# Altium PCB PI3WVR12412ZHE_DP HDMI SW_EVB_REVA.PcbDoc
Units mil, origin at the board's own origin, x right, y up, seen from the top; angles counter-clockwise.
Board outline 3803 x 3400 mil, 4 copper layers (Top Layer, InternalPlane1, InternalPlane2, Bottom Layer); 70 components, 74 nets, 324 pads, 131 vias.
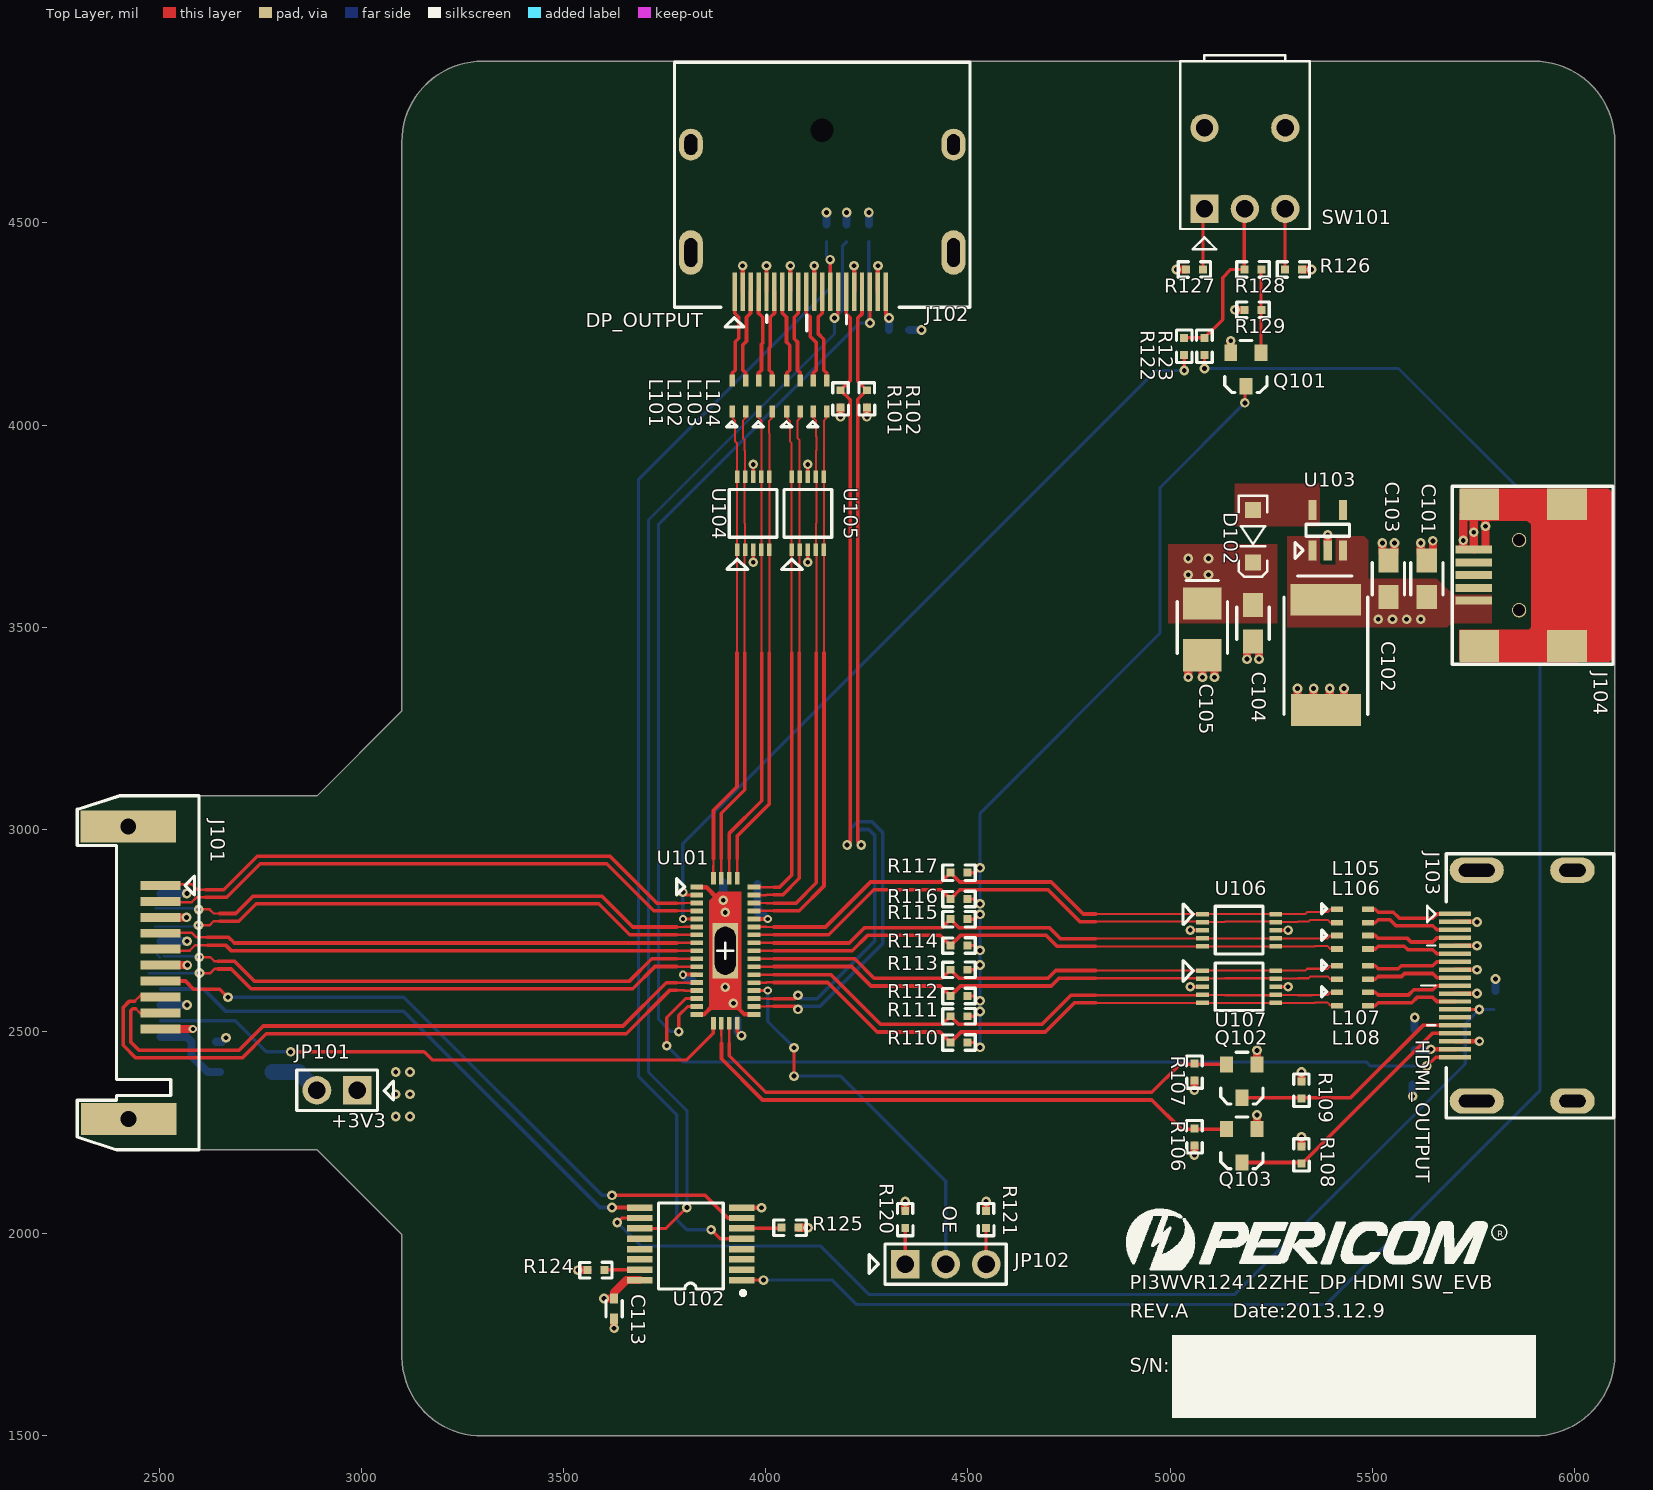
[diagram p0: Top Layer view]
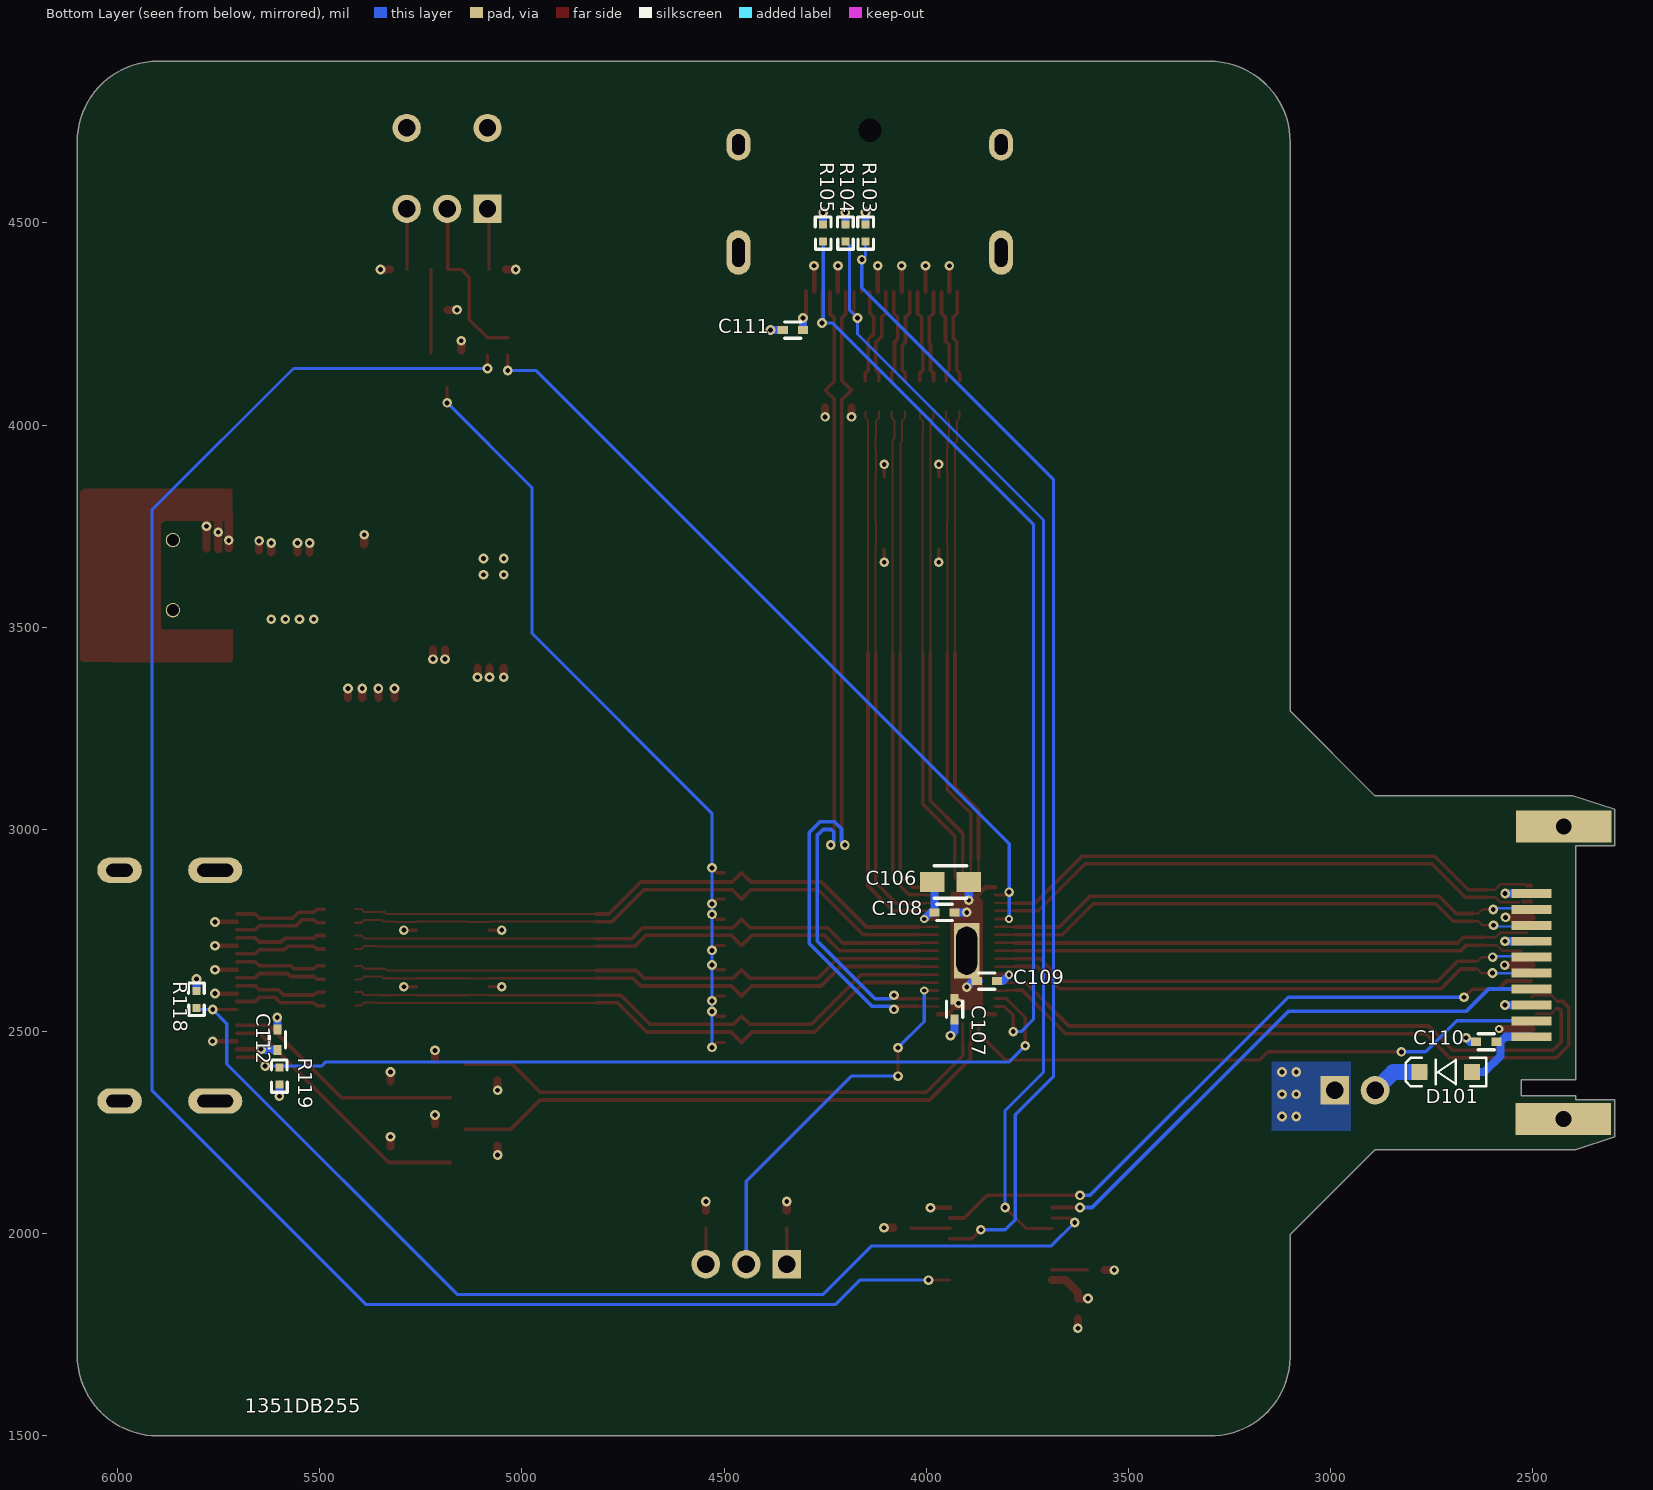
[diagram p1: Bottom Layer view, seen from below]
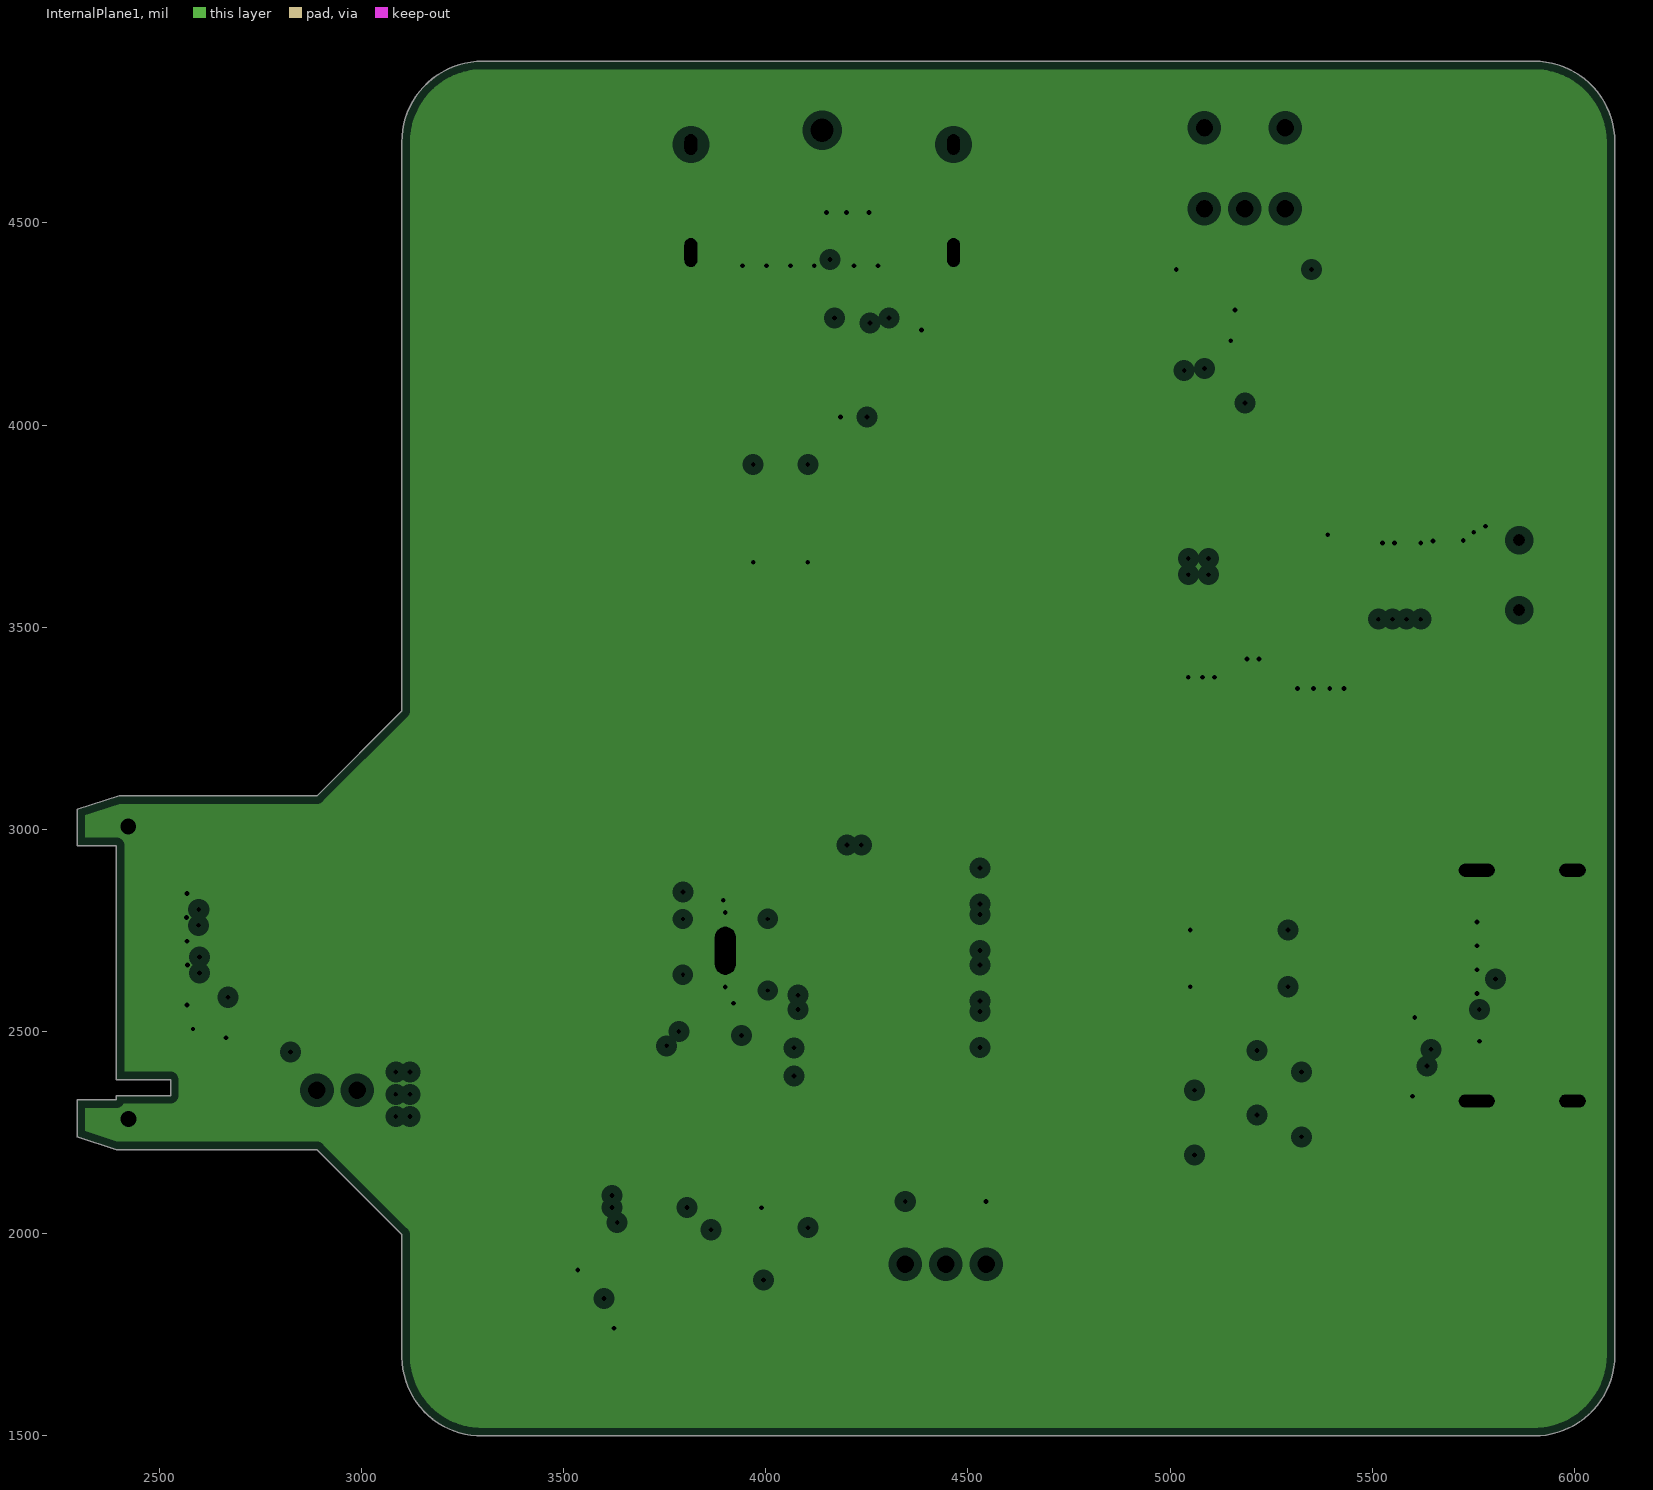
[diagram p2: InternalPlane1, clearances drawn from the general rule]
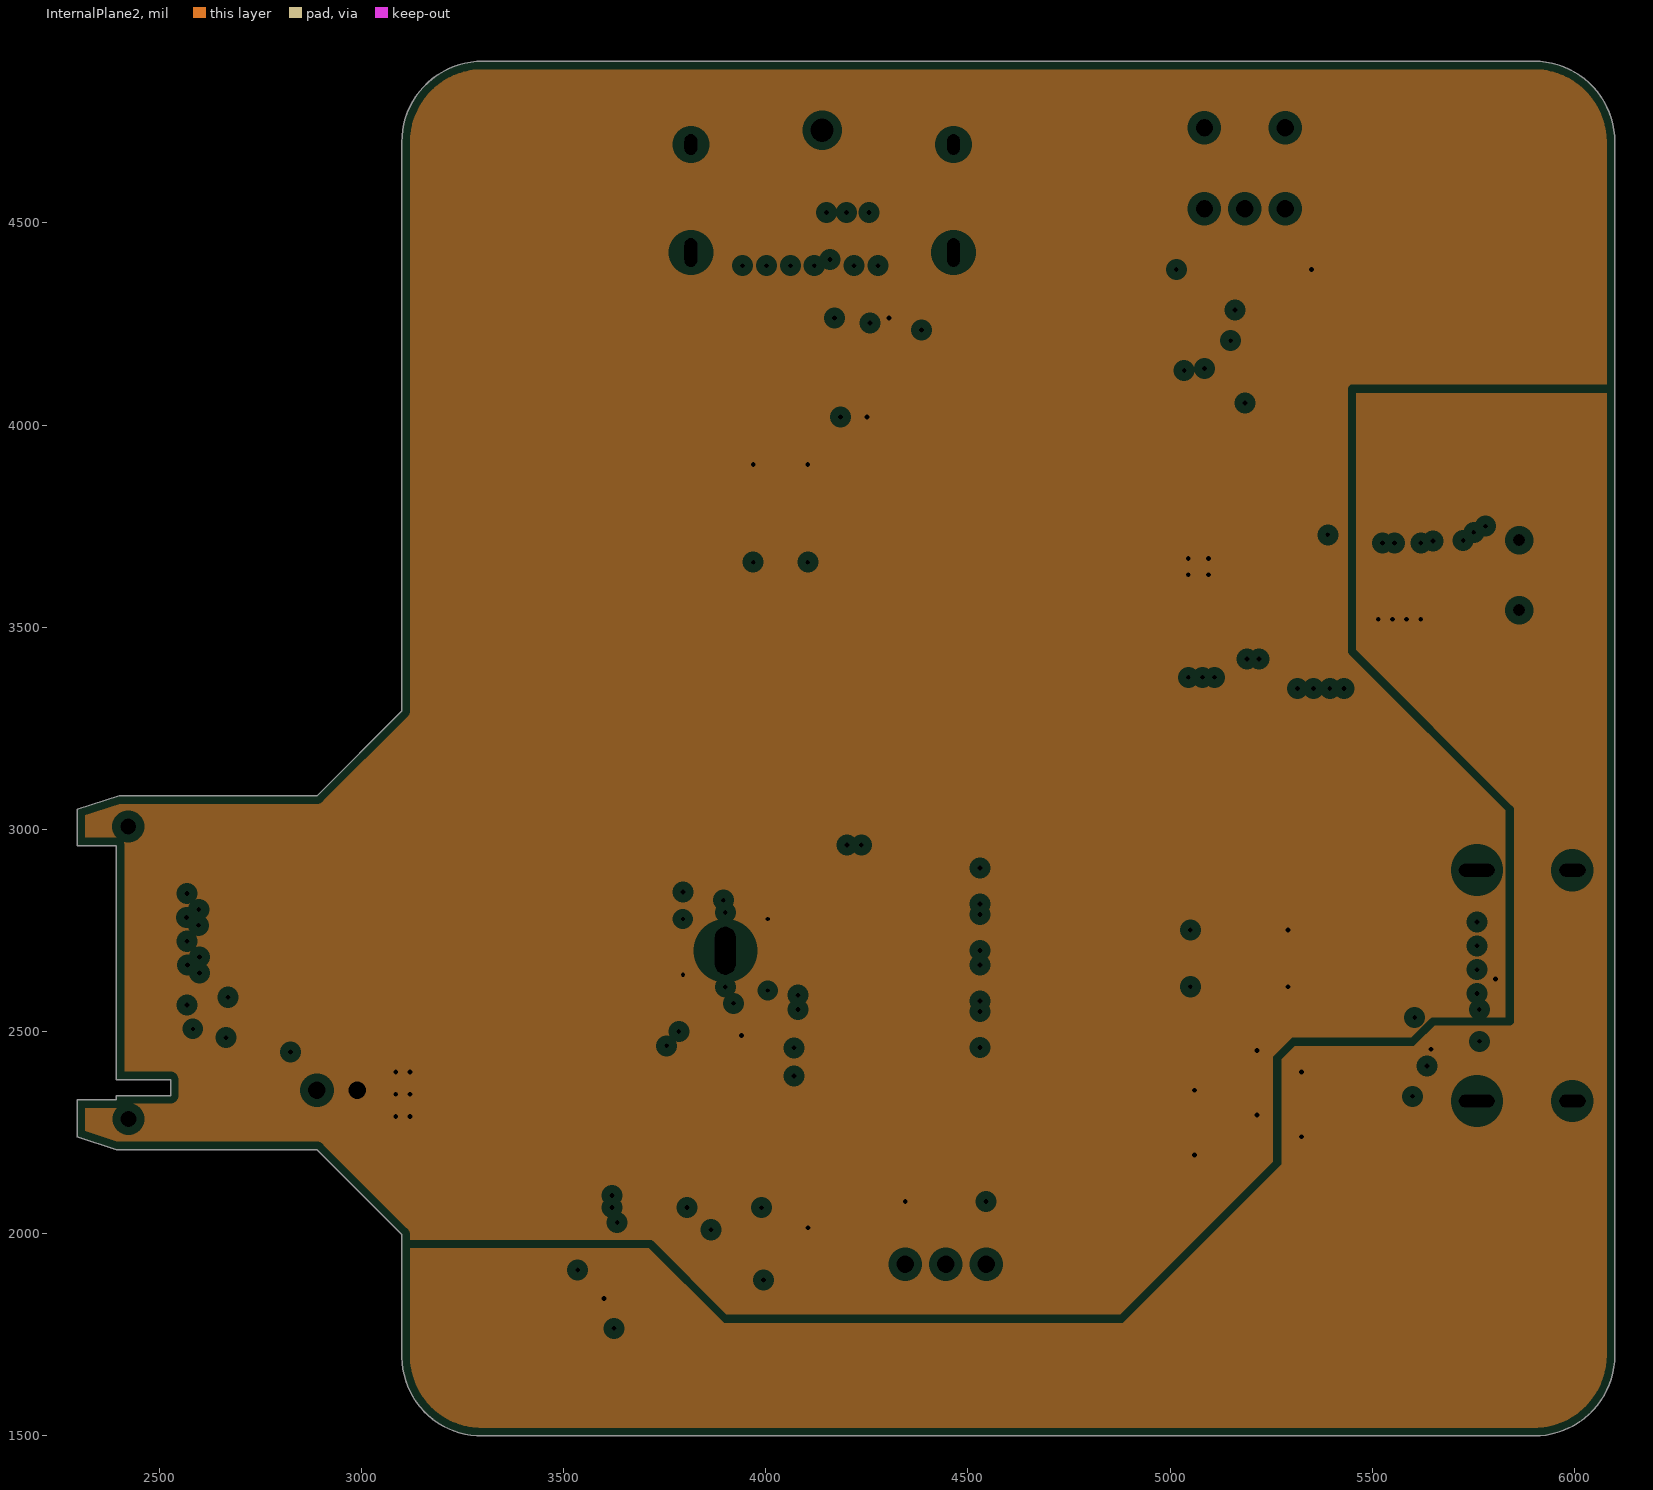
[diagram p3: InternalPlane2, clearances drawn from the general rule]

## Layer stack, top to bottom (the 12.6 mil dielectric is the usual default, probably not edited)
Top Layer: signal copper 1.4
Dielectric: core 12.6, FR-4, Dk 4.8
InternalPlane1: plane copper 1.4, net GND
Dielectric: prepreg 12.6, FR-4, Dk 4.8
InternalPlane2: plane copper 1.4, net +3V3
Dielectric: core 12.6, FR-4, Dk 4.8
Bottom Layer: signal copper 1.4

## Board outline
2297,2240 2394,2208 2890,2208 3100,1998 3100,1695 ccw(c3297.5,1697.5) 3300,1500 5900,1500 ccw(c5900,1700) 6100,1700 6100,4700 ccw(c5900,4700) 5900,4900 3300,4900 ccw(c3300,4700) 3100,4700 3100,3293 2890,3083 2401,3083 2297,3050 2297,2960 2394,2960 2394,2381 2528,2381 2528,2342 2394,2342 2394,2331 2297,2331

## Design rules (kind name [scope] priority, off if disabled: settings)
Clearance [All] p1: gap=5
ComponentClearance [All] p1: gap=0 collisioncheckmode=3 verticalgap=0
DiffPairsRouting [All] p1: maxlimit=10 minlimit=10 mostfreqgap=10 maxuncoupledlength=500
HoleSize [All] p1: absolutevalues=TRUE maxlimit=500 minlimit=1 maxpercent=80.000 minpercent=20.000
PlaneClearance [All] p1: clearance=20
PlaneConnect [All] p1: planeconnectstyle=Direct reliefexpansion=20 reliefentries=4 reliefconductorwidth=10 reliefairgap=10
PolygonConnect [All] p1: connectstyle=Direct reliefconductorwidth=10 reliefentries=4 polygonreliefangle="90 Angle"
RoomDefinition "PI3WVR12412_DP HDMI_EVB" [InComponentClass('PI3WVR12412_DP HDMI_EVB')] p1: confinementstyle=ConfineIn formatcopy=TRUE lockcomponents=FALSE outline 120,25 27240,25 27240,6930 120,6930
RoutingVias [All] p1: holewidth=28 width=50 viastyle="Through Hole" minholewidth=8 minwidth=10 maxholewidth=28 maxwidth=50
SolderMaskExpansion [All] p1: expansion=4
TestPointUsage [All] p1: valid=0 allowmultiple=FALSE
Testpoint [All] p1: side=15 testpointundercomponent=TRUE minsize=40 maxsize=100 preferedsize=60 minholesize=0 maxholesize=40 preferedholesize=32 testpointgrid=1 style=1023 order=0123456789
Width [All] p1: maxlimit=150 minlimit=5 preferedwidth=10
14 further rules are at their usual default settings.

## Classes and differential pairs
differential pair NewDifferentialPair9: +AUX-_A -AUX+_A
differential pair NewDifferentialPair8: +D3-_DP -D3+_DP
differential pair NewDifferentialPair7: +D2-_DP -D2+_DP
differential pair NewDifferentialPair6: +D1-_DP -D1+_DP
differential pair NewDifferentialPair5: +D0-_DP -D0+_DP
differential pair NewDifferentialPair4: +D2-_HDMI -D2+_HDMI
differential pair NewDifferentialPair3: +D1-_HDMI -D1+_HDMI
differential pair NewDifferentialPair2: +CK-_HDMI -CK+_HDMI
differential pair NewDifferentialPair1: +D0-_HDMI -D0+_HDMI

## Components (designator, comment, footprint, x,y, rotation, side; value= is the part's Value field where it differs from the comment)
C101 "4.7u" CAP@CC_0805 5635,3620 r90 top
C102 "100u" CAP@CT_7343 5385,3450 r90 top
C103 "1u" CAP@CC_0805 5540,3620 r90 top
C104 "1u" CAP@CC_0805 5205,3510 r270 top
C105 "22u" CAP@CT_3528 5080,3495 r270 top
C106 "4.7u" CC_0805 3940,2870 r0 bottom
C107 "0.1u" CC_0402 3930,2555 r270 bottom
C108 "0.1u" CC_0402 3955,2795 r0 bottom
C109 "0.1u" CC_0402 3850,2625 r180 bottom
C110 "0.1u" CC_0402 2615,2475 r0 bottom
C111 "0.1u" CC_0402 4330,4235 r180 bottom
C112 "0.1u" CC_0402 5605,2480 r270 bottom
C113 "0.1u" CC_0402 3625,1815 r90 top
D101 "B0520LW" D@SOD-123 2715,2400 r0 bottom
D102 "B0520LW" D@SOD-123 5205,3725 r270 top
J101 "DP PLUG" CON_DP_PLUG 2405,2645 r90 top
J102 "CON_DP_Source_Recept" CON_DP_Recept 4139.63,4526.85 r180 top locked
J103 "CON_HDMI_Recept" CON_HDMI_Recept 5716,2791 r90 top
J104 "CON_USB2.0_MiniB_SMT" CON_USB2.0_MiniB_SMT 6070,3629 r180 top
JP101 "2x1 Pin Header" "2x1 Pin Header" 2990,2355 r180 top
JP102 "3x1 Pin Header" "3x1 Pin Header" 4345,1925 r0 top
L101 "ACM2012H" ACM2012H 3934,4072 r90 top
L102 "ACM2012H" ACM2012H 3999,4072 r90 top
L103 "ACM2012H" ACM2012H 4069,4072 r90 top
L104 "ACM2012H" ACM2012H 4134,4072 r90 top
L105 "ACM2012H" ACM2012H 5451,2786 r0 top
L106 "ACM2012H" ACM2012H 5451,2721 r0 top
L107 "ACM2012H" ACM2012H 5451,2646 r0 top
L108 "ACM2012H" ACM2012H 5451,2581 r0 top
Q101 "2N7002" SOT-23-1 5225,4175 r180 top
Q102 "2N7002" SOT-23-1 5215,2415 r180 top
Q103 "2N7002" SOT-23-1 5215,2255 r180 top
R101 "100K" RES@R_0402 4185,4065 r90 top
R102 "100K" RES@R_0402 4250,4065 r90 top
R103 "1M" RES@R_0402 4150,4475 r270 bottom
R104 "1M" RES@R_0402 4200,4475 r270 bottom
R105 "100K" R_0402 4255,4475 r270 bottom
R106 "2K2" R_0402 5060,2240 r270 top
R107 "2K2" R_0402 5060,2400 r270 top
R108 "2K2" R_0402 5325,2195 r90 top
R109 "2K2" R_0402 5325,2355 r90 top
R110 "499" R_0402 4478,2473 r180 top
R111 "499" R_0402 4478,2538 r180 top
R112 "499" R_0402 4478,2588 r180 top
R113 "499" R_0402 4478,2653 r180 top
R114 "499" R_0402 4478,2713 r180 top
R115 "499" R_0402 4478,2778 r180 top
R116 "499" R_0402 4478,2828 r180 top
R117 "499" R_0402 4478,2893 r180 top
R118 "27K" R_0402 5805,2580 r270 bottom
R119 "100K" R_0402 5600,2390 r90 bottom
R120 "4K7" RES@R_0402 4345,2035 r90 top
R121 "4K7" RES@R_0402 4545,2035 r90 top
R122 "100" RES@R_0402 5035,4195 r270 top
R123 "100" RES@R_0402 5085,4195 r270 top
R124 "4K7" R_0402 3580,1910 r180 top
R125 "100K" R_0402 4060,2015 r180 top
R126 "4K7" R_0402 5305,4385 r0 top
R127 "4K7" R_0402 5060,4385 r0 top
R128 "100" R_0402 5205,4385 r180 top
R129 "100K" R_0402 5205,4285 r0 top
SW101 "SPDT" SWSPDT@SWSPDT 5085,4535 r180 top
U101 "PI3WVR12412ZHE@TQFN42" TQFN42 3900,2700 r270 top
U102 "PI5C3257LE@TSSOP16" TSSOP16 3815,1975 r90 top
U103 "PT7M8206" Pow_SOT-23-5 5390,3740 r180 top
U104 "RClamp0544M" MSOP10 3969,3782 r0 top
U105 "RClamp0544M" MSOP10 4104,3782 r0 top
U106 "RClamp0544M" MSOP10 5171,2751 r270 top
U107 "RClamp0544M" MSOP10 5171,2611 r270 top
? "Comment" PSC_LOG 5000,2015 r0 top

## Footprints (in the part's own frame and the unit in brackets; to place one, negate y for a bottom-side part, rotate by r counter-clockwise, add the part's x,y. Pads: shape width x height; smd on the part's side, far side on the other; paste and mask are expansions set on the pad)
"2x1 Pin Header" [mm] "Pin Header 2x1 Pitch 2.54mm"
  rect 1.8x1.8 hole 1.1: 1(0,0)
  round 1.8 hole 1.1: 2(2.54,0)
  silkscreen extent -2.27,-1.27 3.81,1.27
"3x1 Pin Header" [mm] "Pin Header 3x1 Pitch 2.54mm"
  rect 1.8x1.8 / inner round 1.8 / far side rect 1.8x1.8 hole 1.1: 1(0,0)
  round 1.8 hole 1.1: 2(2.54,0) 3(5.08,0)
  silkscreen extent -2.27,-1.27 6.35,1.27
ACM2012H [mm]
  rect 0.75x0.35 smd: 1(-0.975,0.425) 2(0.975,0.425) 3(-0.975,-0.425) 4(0.975,-0.425)
  silkscreen extent -1.92,0.12 -1.6,0.78
CAP@CC_0805 [mil]
  rect 60x50 smd: 1(-45,0) 2(45,0)
  silkscreen extent -40,-40 40,40
CAP@CT_3528 [mil]
  rect 80x95 smd: 1(-64,0) 2(64,0)
  silkscreen extent -121,-62 60,62
CAP@CT_7343 [mm]
  rect 2x4.4 smd: 1(3,0) 2(-3.926,-0.011)
  silkscreen extent -4.19,-2.64 4.5,2.62
CC_0402 [mil]
  rect 25x20 smd: 1(-25,0) 2(25,0)
  silkscreen extent -20,-20 20,20
CC_0805 [mil]
  rect 60x50 smd: 1(-45,0) 2(45,0)
  silkscreen extent -40,-40 40,40
CON_DP_PLUG [mm]
  rect 0.56x2.5 smd: 1(5.495,-2.5) 3(4.495,-2.5) 5(3.495,-2.5) 7(2.495,-2.5) 9(1.495,-2.5) 11(0.495,-2.5) 13(-0.505,-2.5) 15(-1.505,-2.5) 17(-2.505,-2.5) 19(-3.505,-2.5)
  rect 0.56x2.5 smd far side: 2(4.995,-2.5) 4(3.995,-2.5) 6(2.995,-2.5) 8(1.995,-2.5) 10(0.995,-2.5) 12(-0.005,-2.5) 14(-1.005,-2.5) 16(-2.005,-2.5) 18(-3.005,-2.5) 20(-4.005,-2.5)
  rect 2x6 hole 1: 21(-9.166,-0.493) 21(9.206,-0.469)
  silkscreen extent -11.11,-4.92 11.14,2.74
CON_DP_Recept [mm]
  rect 0.28x2.4 smd: 1(5.5,5) 2(5,5) 3(4.5,5) 4(4,5) 5(3.5,5) 6(3,5) 7(2.5,5) 8(2,5) 9(1.5,5) 10(1,5) 11(0.5,5) 12(0,5) 13(-0.5,5) 14(-1,5) 15(-1.5,5) 16(-2,5) 17(-2.5,5) 18(-3,5) 19(-3.5,5) 20(-4,5)
  oval 1.5x2.8 hole 0.8 slot 1.8 at 90 deg: 21(-8.25,2.54) 22(8.25,2.54)
  oval 1.5x2 hole 0.8 slot 1.3 at 90 deg: 23(-8.25,-4.24) 24(8.25,-4.24)
  round 0 hole 1.45 unplated: 25(0,-5.14)
  silkscreen extent -9.29,-9.42 9.28,7.47
CON_HDMI_Recept [mm]
  rect 0.28x2 smd: 1(0,0.281) 2(-0.5,0.281) 3(-1,0.281) 4(-1.5,0.281) 5(-2,0.281) 6(-2.5,0.281) 7(-3,0.281) 8(-3.5,0.281) 9(-4,0.281) 10(-4.5,0.281) 11(-5,0.281) 12(-5.5,0.281) 13(-6,0.281) 14(-6.5,0.281) 15(-7,0.281) 16(-7.5,0.281) 17(-8,0.281) 18(-8.5,0.281) 19(-9,0.281)
  oval 1.6x3.4 hole 0.8 slot 2.25 at 90 deg: 20(-11.75,-1.08) 21(2.75,-1.08)
  oval 1.6x2.8 hole 0.8 slot 1.65 at 90 deg: 22(-11.75,-7.09) 23(2.75,-7.09)
  silkscreen extent -12.82,-9.68 3.78,2.41
CON_USB2.0_MiniB_SMT [mm]
  rect 2.3x0.5 smd: 1(8.1,1.6) 2(8.1,0.8) 3(8.1,0) 4(8.1,-0.8) 5(8.1,-1.6)
  rect 2.5x2 smd: 5(2.25,4.45) 5(2.25,-4.45) 5(7.75,-4.45) 5(7.75,4.45)
  round 0.9 hole 0.762 unplated: 10(5.25,-2.2) 11(5.25,2.2)
  Top Layer region: 1.58,5.45 -0.35,5.45 -0.438,5.432 -0.513,5.383 -0.562,5.308 -0.58,5.22 -0.58,5.22 -0.58,-5.09 -0.553,-5.224 -0.477,-5.337 -0.364,-5.413 -0.23,-5.44 -0.23,-5.44 8.81,-5.44 8.875,-5.427 8.93,-5.39 8.967,-5.335 8.98,-5.27 8.98,-5.27 8.98,-3.59 8.968,-3.529 8.933,-3.477 8.881,-3.442 8.82,-3.43 8.82,-3.43 4.93,-3.43 4.758,-3.396 4.612,-3.298 4.514,-3.152 4.48,-2.98 4.48,-2.98 4.48,3.17 4.5,3.269 4.556,3.354 4.641,3.41 4.74,3.43 4.74,3.43 8.93,3.43 8.964,3.437 8.994,3.456 9.013,3.486 9.02,3.52 9.02,3.52 9.02,5.26 9.004,5.34 8.958,5.408 8.89,5.454 8.81,5.47 8.81,5.47 1.6,5.47 1.592,5.468 1.586,5.464 1.582,5.458 1.58,5.45
  silkscreen extent -0.65,-5.59 9.45,5.6
D@SOD-123 [mil]
  rect 40x40 smd: 1(-65,0) 2(65,0)
  silkscreen extent -100,-35 100,35
MSOP10 [mm]
  rect 0.28x0.8 smd: 1(-1,-2.3) 2(-0.5,-2.3) 3(0,-2.3) 4(0.5,-2.3) 5(1,-2.3) 6(1,2.3) 7(0.5,2.3) 8(0,2.3) 9(-0.5,2.3) 10(-1,2.3)
  silkscreen extent -1.65,-3.52 1.5,1.5
Pow_SOT-23-5 [mil]
  rect 20x50 smd: 1(37.5,50) 2(0,50) 3(-37.5,50) 4(-37.5,-50) 5(37.5,-50)
  silkscreen extent -54,-15 81,70
PSC_LOG [mil]
  silkscreen extent -107,-103 833,45
R_0402 [mm]
  rect 0.5x0.5 smd: 1(-0.532,-0.001) 2(0.54,-0.001)
  silkscreen extent -1.02,-0.49 1.02,0.49
RES@R_0402 [mm]
  rect 0.5x0.5 smd: 1(-0.532,-0.001) 2(0.54,-0.001)
  silkscreen extent -1.02,-0.49 1.02,0.49
SOT-23-1 [mil]
  rect 32.01x40 smd: 1(0,-3.94) 2(75,-3.94) 3(37.48,78.74)
  silkscreen extent -15,-34 90,94
SWSPDT@SWSPDT [mil]
  rect 70x70 / inner round 70 / far side rect 70x70 hole 43: 1(0,0)
  round 70 hole 43: 2(-100,0) 3(-200,0) 4(-200,-200) 5(0,-200)
  silkscreen extent -260,-380 60,100
TQFN42 [mm]
  rect 0.3x0.8 smd: 1(-4,-1.8) 2(-3.5,-1.8) 3(-3,-1.8) 4(-2.5,-1.8) 5(-2,-1.8) 6(-1.5,-1.8) 7(-1,-1.8) 8(-0.5,-1.8) 9(0,-1.8) 10(0.5,-1.8) 11(1,-1.8) 12(1.5,-1.8) 13(2,-1.8) 14(2.5,-1.8) 15(3,-1.8) 16(3.5,-1.8) 17(4,-1.8) 22(4,1.8) 23(3.5,1.8) 24(3,1.8) 25(2.5,1.8) 26(2.007,1.8) 27(1.5,1.8) 28(1,1.8) 29(0.5,1.8) 30(0,1.8) 31(-0.5,1.8) 32(-1,1.8) 33(-1.5,1.8) 34(-2,1.8) 35(-2.5,1.8) 36(-3,1.8) 37(-3.5,1.8) 38(-4,1.8)
  rect 0.8x0.3 smd: 18(4.55,-0.75) 19(4.55,-0.25) 20(4.55,0.25) 21(4.55,0.75) 39(-4.55,0.75) 40(-4.55,0.25) 41(-4.55,-0.25) 42(-4.55,-0.75)
  rect 3.5x1.6 hole 1.3 slot 3 at 0 deg: 43(0,0)
  Top Layer region: -3.72,1.01 3.7,1.01 3.7,-1.01 -3.14,-1.01 -3.72,-0.43
  silkscreen extent -4.52,-3.05 0.5,0.5
TSSOP16 [mm] "CHS-08TA"
  rect 0.4x1.6 smd: 1(-2.275,-3.204) 2(-1.625,-3.204) 3(-0.975,-3.204) 4(-0.325,-3.204) 5(0.325,-3.204) 6(0.975,-3.204) 7(1.625,-3.204) 8(2.275,-3.204) 9(2.275,3.204) 10(1.625,3.204) 11(0.975,3.204) 12(0.325,3.204) 13(-0.325,3.204) 14(-0.975,3.204) 15(-1.625,3.204) 16(-2.275,3.204)
  silkscreen extent -3.21,-3.4 2.58,2.04

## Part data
C101 C103 C104: library part "CHIP CAP0805"
C102: library part "100UF 7343_1"
C105: library part "22UF 3528"
C106 C107 C108 C109 C110 C111 C112 C113: library part C_0.1u_0402
D101 D102: library part SchottkyDiode@SOD-123_1
J101: library part CONN_DP_4
J102: library part CON_DP_Source_Recept_1
L101 L102 L103 L104 L105 L106 L107 L108: library part CMT908
Q101 Q102 Q103: library part 2N6659
R101 R102 R103 R104 R120 R121 R122 R123: library part "CHIP RES0402_1"
R105 R106 R107 R108 R109 R110 R111 R112 R113 R114 R115 R116 R117 R118 R119 R124 R125 R126 R127 R128 R129: library part R_0402
SW101: library part "SW SPDT_0"
U101: library part PI3HDMI20412ZHE@TQFN42_0
U102: library part PI6C10806LE@TSSOP16_0
U103: library part Pow_PT7M8206
U104 U106: library part RBO4040/SO_9
U105 U107: library part RBO4040/SO_10

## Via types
v1: diameter 24, hole 12, Top Layer to Bottom Layer, tented both sides, 126 vias
v2: diameter 20, hole 10, Top Layer to Bottom Layer, tented both sides, 5 vias

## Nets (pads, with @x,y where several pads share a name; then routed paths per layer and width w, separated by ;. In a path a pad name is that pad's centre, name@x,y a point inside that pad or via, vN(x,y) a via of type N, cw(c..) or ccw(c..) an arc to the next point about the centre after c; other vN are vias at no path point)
+3V3: C104.1 C105.1 C106.2 C107.2 C108.2 C109.2 C111.2 D102.2 J102.20 JP101.1 Q102.1 Q103.1 R102.1 R106.2 R107.2 R118.1 R120.2 R125.1 R126.2 U101.12 U101.21 U101.34 U104.8 U105.8 U106.8 U107.8 | length 718.9
  Top Layer w9: U101.21 3929.53,2500.47 v1(3940,2490) ; U104.8 v1(3969,3903) ; U105.8 v1(4104,3903) ; U107.8 v1(5292,2611) ; U106.8 v1(5292,2751)
  Top Layer w10: v2@3795.26,2640.94 U101.12 ; U101.34 v2@4004.74,2778.74 ; J102.20 4297.11,4272.89 v1(4305,4265)
  Top Layer w20: R125.1 v1(4104.65,2015.03) ; v1(4250.03,4020.35) R102.1 ; R120.2 v1(4345.03,2079.97) ; v1(5059.97,2195.03) R106.2 ; v1(5059.97,2355.03) R107.2 ; Q103.1@5215,2270 v1(5215,2293.7) ; Q102.1@5215,2430 v1(5215,2453.7) ; R126.2 v1(5349.97,4384.97)
  Bottom Layer w20: v2(3795,2640.69) 3810.69,2625 C109.2@3820,2625 ; C107.2 3930,2500 v1(3940,2490) ; C106.2@3980,2865 C108.2 3989,2795 v2(4005,2779) ; C111.2 v1(4305,4265) ; R118.1 v1(5805.03,2629.97)
  other v1: 3085,2290 3120,2290 3085,2345 3120,2345 3085,2400 3120,2400 5045,3630 5095,3630 5045,3670 5095,3670
+3V3_DP: C110.1 D101.1 J101.20 | length 203.2
  Bottom Layer w20: J101.20 2567.58,2487.32 2579.9,2475 2579.9,2440.1 2620,2400 D101.1
+3V3_USB: D102.1 U103.5
+5V: C101.1 C102.1 C103.1 C112.2 C113.2 J103.18 J104.1 R108.2 R109.2 U102.16 U103.1 U103.3 | length 264.4
  Top Layer w11: v1(5645,2456.35) J103.18
  Top Layer w20: v1(3600,1840) C113.2 3625,1855 3655.43,1885.43 U102.16 ; R108.2 v1(5325.03,2239.97) ; R109.2 v1(5325.03,2399.97)
  Bottom Layer w20: C112.2 5643.65,2455 v1(5645,2456.35)
  other v1: 5515,3520 5550,3520 5585,3520 5620,3520
AUX+: J101.15 U101.14 | length 1700.4
  Top Layer w6: 2439.56,2575.56 2453.61,2589.61 2499.57,2589.61 J101.15 ; 3779.95,2601.92 3798.04,2601.92 3798.39,2601.57 U101.14
  Top Layer w9: 2439.56,2575.56 2426.69,2575.56 2411,2559.87 2411,2466.13 2442.13,2435 2705,2435 2765,2495 3655,2495 3761.92,2601.92 3779.95,2601.92
AUX+_A: J102.15 R101.2 U101.23 | length 2200.7
  Top Layer w6: U101.23 4001.61,2562.2 4001.96,2562.55 4020.05,2562.55
  Top Layer w9: 4020.05,2562.55 4072.45,2562.55 v1(4080,2555) ; J102.15 4198.69,4275 4208.87,4264.82 4208.87,4110.11 R101.2 4208.87,4062.43 v1@4208.87,2970 ; v1(4201.32,2961.55) v1@4208.87,2969.09
  Bottom Layer w9: v1(4080,2555) 4087.55,2562.55 4134.42,2562.55 4289,2717.13 4289,2992.87 4262.87,3019 4227.13,3019 4209.78,3001.65 v1@4209.78,2969.09 ; v1(4201.32,2961.55) v1@4209.78,2970
AUX+_B: Q102.2 R107.1 U101.20 | length 1377
  Top Layer w6: 3909.5,2471.68 3909.5,2489.78 3909.84,2490.12 U101.20
  Top Layer w9: 3909.5,2471.68 3909.5,2440.5 4000,2350 4955,2350 5023.94,2418.94 Q102.2
AUX-: J101.17 U101.13 | length 1623.4
  Top Layer w6: 2442,2556.56 2453.96,2544.61 J101.17@2491.85,2544.61 ; 3779.95,2620.92 3798.04,2620.92 3798.39,2621.26 U101.13
  Top Layer w9: 2442,2556.56 2434.56,2556.56 2430,2552 2430,2474 2450,2454 2697.13,2454 2757.13,2514 3647.13,2514 3754.05,2620.92 3779.95,2620.92
AUX-_A: J102.17 R102.2 U101.24 | length 2105.6
  Top Layer w6: U101.24 4001.61,2581.89 4001.96,2581.55 4020.05,2581.55
  Top Layer w9: 4020.05,2581.55 4071.55,2581.55 v1(4080,2590) ; v1(4236.32,2961.55) 4227.87,2970 4227.87,4064.11 R102.2 4227.87,4108.43 4227.87,4264.82 4238.06,4275 J102.17
  Bottom Layer w9: v1(4080,2590) 4088.45,2581.55 4126.55,2581.55 4270,2725 4270,2985 4255,3000 4235,3000 4228.78,2993.78 4228.78,2969.09 v1(4236.32,2961.55)
AUX-_B: Q103.2 R106.1 U101.19 | length 1409.8
  Top Layer w6: U101.19 3890.16,2490.12 3890.5,2489.78 3890.5,2471.68
  Top Layer w9: 3890.5,2471.68 3890.5,2432.63 3992.13,2331 4955,2331 5027.06,2258.94 Q103.2
CAB_DET: J101.13 U102.7 | length 1680.5
  Top Layer w9: J101.13 2564.88,2625.12 2585,2605 2650,2605 v1(2670,2585) ; v1(3620,2095) 3850,2095 3906.02,2038.98 U102.7
  Bottom Layer w9: v1(2670,2585) 3105,2585 3595,2095 v1(3620,2095)
CAB_DET_A: J102.13 R103.2 U102.5 | length 2918.4
  Top Layer w8: J102.13 v1(4159.31,4409.31)
  Top Layer w9: v1(3865,2010) 3887.2,1987.8 U102.5
  Bottom Layer w8: v1(3865,2010) 3805,2010 3780,2035 3780,2294.64 3685,2389.64 3685,3865 4159.31,4339.31 v1(4159.31,4409.31) 4150.03,4418.6 R103.2
CAB_DET_B: R125.2 U102.6 | length 95.9
  Top Layer w9: U102.6 R125.2@4037.09,2013.39
CEC: J101.14 U102.9 | length 1408.9
  Top Layer w9: v1(3620,2065) U102.9@3688.43,2065
  Bottom Layer w9: J101.14 2609.57,2605.43 2665,2550 3105,2550 3590,2065 v1(3620,2065)
CEC_A: J102.14 R104.2 U102.11 | length 2837.3
  Top Layer w8: U102.11 3753.39,2013.39 v1(3805,2065) ; v1(4170,4265) 4179,4274 J102.14
  Bottom Layer w8: v1(3805,2065) 3805,2305 3710,2400 3710,3765.36 4170,4225.36 v1(4170,4265) 4190,4285 4190,4443.7 R104.2
CEC_B: J103.13 R118.2 U102.10 | length 2713.1
  Top Layer w8: v1(3632.72,2027.95) 3643.74,2038.98 U102.10 ; J103.13 v1(5764.78,2554.78)
  Bottom Layer w8: v1(3632.72,2027.95) 3690.67,1970 4135,1970 4255,1850 5160,1850 5730,2420 5730,2520 v1(5764.78,2554.78) R118.2@5801.08,2554.78
CK+_HDMI: J103.10 L108.2 | length 228.2
  Top Layer w9: L108.2 5507.77,2597.73 5515,2590.5 5589.5,2590.5 5602.65,2603.65 5649.82,2603.65 5660,2613.83 J103.10
CK-_HDMI: J103.12 L108.4 | length 228.2
  Top Layer w9: L108.4 5507.77,2564.27 5515,2571.5 5597.37,2571.5 5610.52,2584.65 5649.82,2584.65 5660,2574.46 J103.12
D0+: J101.1 U101.3 | length 1409
  Top Layer w6: J101.1@2520,2865 2580,2865 2593.85,2851.15 2615.32,2851.15 ; 3779.95,2817.77 3798.04,2817.77 3798.39,2818.11 U101.3
  Top Layer w9: J101.1 J101.1@2515,2861.34 ; 2615.32,2851.15 2659.28,2851.15 2742.13,2934 3615,2934 3731.23,2817.77 3779.95,2817.77
D0+_A: L101.1 U101.42 U104.1 U104.10 | length 1184.1
  Top Layer w5: L101.1 3917.27,4017.73 3924.5,4010.5 3924.5,3964 3924.5,3960.06 3928.97,3955.59 3928.97,3937.34 3928.63,3937 3928.63,3881.8 3928.97,3881.46 3928.97,3814.53 3928.97,3757.34 3928.63,3757 3928.63,3700.7 3928.97,3700.36 3928.97,3437
  Top Layer w6: U101.42 3870.47,2909.88 3870.81,2910.22 3870.81,2928.32
  Top Layer w9: 3870.81,2928.32 3870.82,3047.69 3928.97,3105.84 3928.97,3437
D0+_B: L105.1 R117.2 U101.33 U106.1 U106.10 | length 1545.2
  Top Layer w5: 4816,2791.03 5079.36,2791.03 5079.7,2791.37 5136,2791.37 5136.34,2791.03 5193.53,2791.03 5260.46,2791.03 5260.8,2791.37 5316,2791.37 5316.34,2791.03 5334.59,2791.03 5339.06,2795.5 5343,2795.5 5389.5,2795.5 5396.73,2802.73 L105.1
  Top Layer w6: U101.33 4001.61,2759.06 4001.96,2758.71 4020.05,2758.71
  Top Layer w9: 4020.05,2758.71 4147.71,2758.71 4259,2870 4423.75,2870 4433.7,2870 R117.2 4479.76,2870 4491.32,2870 4706,2870 4784.97,2791.03 4816,2791.03
D0+_DP: J102.1 L101.2 | length 230.5
  Top Layer w9: L101.2 3917.27,4128.77 3924.5,4136 3924.5,4206.37 3933.28,4215.15 3933.28,4266.67 3923.09,4276.85 J102.1
D0+_HDMI: J103.7 L107.2 | length 225.8
  Top Layer w9: L107.2 5507.77,2662.73 5515,2655.5 5564.5,2655.5 5571.7,2662.7 5649.82,2662.7 5660,2672.89 J103.7
D0-: J101.3 U101.4 | length 1403.3
  Top Layer w6: J101.3@2535,2820 2580,2820 2592.15,2832.15 2613.87,2832.15 ; 3779.95,2798.77 3798.04,2798.77 3798.39,2798.43 U101.4
  Top Layer w9: J101.3 J101.3@2525,2821.97 ; 2613.87,2832.15 2667.15,2832.15 2750,2915 3607.13,2915 3723.36,2798.77 3779.95,2798.77
D0-_A: L101.3 U101.41 U104.2 U104.9 | length 1184.1
  Top Layer w5: 3947.97,3437 3947.97,3700.36 3948.32,3700.7 3948.32,3757 3947.97,3757.34 3947.97,3881.46 3948.32,3881.8 3948.32,3937 3947.97,3937.34 3947.97,3963.46 3943.5,3967.94 3943.5,4010.5 3950.73,4017.73 L101.3
  Top Layer w6: 3889.81,2928.32 3889.81,2910.22 3890.16,2909.88 U101.41
  Top Layer w9: 3889.81,2928.32 3889.82,3039.82 3947.97,3097.97 3947.97,3437
D0-_B: L105.3 R116.2 U101.32 U106.2 U106.9 | length 1545.1
  Top Layer w5: 4816,2772.03 5079.36,2772.03 5079.7,2771.68 5136,2771.68 5136.34,2772.03 5260.46,2772.03 5260.8,2771.68 5316,2771.68 5316.34,2772.03 5342.46,2772.03 5346.94,2776.5 5389.5,2776.5 5396.73,2769.27 L105.3
  Top Layer w6: U101.32 4001.61,2739.37 4001.96,2739.71 4020.05,2739.71
  Top Layer w9: 4020.05,2739.71 4155.58,2739.71 4266.87,2851 4421.38,2851 4433.76,2851 R116.2 4479.7,2851 4494.7,2851 4698.13,2851 4777.1,2772.03 4816,2772.03
D0-_DP: J102.3 L101.4 | length 230.5
  Top Layer w9: L101.4 3950.73,4128.77 3943.5,4136 3943.5,4198.5 3952.28,4207.28 3952.28,4266.67 3962.46,4276.85 J102.3
D0-_HDMI: J103.9 L107.4 | length 225.8
  Top Layer w9: L107.4 5507.77,2629.27 5515,2636.5 5572.37,2636.5 5579.58,2643.7 5649.81,2643.7 5660,2633.52 J103.9
D1+: J101.4 U101.6 | length 1393.3
  Top Layer w6: v1(2597.72,2802.28) 2624.72,2802.28 2634.9,2792.1 2650.35,2792.1 ; 3779.95,2758.71 3798.04,2758.71 3798.39,2759.06 U101.6
  Top Layer w9: 2650.35,2792.1 2689.1,2792.1 2732,2835 3595,2835 3671.29,2758.71 3779.95,2758.71
  Bottom Layer w6: J101.4@2490.71,2805 2595,2805 v1(2597.72,2802.28)
D1+_A: L102.1 U101.40 U104.4 U104.7 | length 1191.5
  Top Layer w5: L102.1 3982.27,4017.73 3989.5,4010.5 3989.5,3976 3989.5,3972.06 3990.03,3971.54 3990.03,3937.34 3989.68,3937 3989.68,3881.8 3990.03,3881.46 3990.03,3840.09 3990.03,3757.34 3989.68,3757 3989.68,3700.7 3990.03,3700.36 3990.03,3437
  Top Layer w6: U101.40 3909.84,2909.88 3910.18,2910.22 3910.18,2928.32
  Top Layer w9: 3910.18,2928.32 3910.19,2991.06 3990.03,3070.9 3990.03,3437
D1+_B: L106.1 R115.2 U101.31 U106.4 U106.7 | length 1490.1
  Top Layer w5: 4816,2729.97 5079.36,2729.97 5079.7,2730.32 5136,2730.32 5136.34,2729.97 5219.09,2729.97 5260.46,2729.97 5260.8,2730.32 5316,2730.32 5316.34,2729.97 5350.54,2729.97 5351.06,2730.5 5355,2730.5 5389.5,2730.5 5396.73,2737.73 L106.1
  Top Layer w6: U101.31 4001.61,2719.68 4001.96,2719.34 4020.05,2719.34
  Top Layer w9: 4020.05,2719.34 4206.34,2719.34 4244,2757 4423.41,2757 4435.7,2757 R115.2 4477.76,2757 4489.97,2757 4701.87,2757 4728.46,2730.41 ; 4728.03,2729.97 4816,2729.97
D1+_DP: J102.4 L102.2 | length 228
  Top Layer w9: J102.4 3982.15,4276.85 3992.33,4266.67 3992.33,4202.33 3989.5,4199.5 3989.5,4136 3982.27,4128.77 L102.2
D1+_HDMI: J103.4 L106.2 | length 226.4
  Top Layer w9: L106.2 5507.77,2737.73 5515,2730.5 5587.37,2730.5 5596.11,2721.76 5649.81,2721.76 5660,2731.94 J103.4
D1-: J101.6 U101.7 | length 1394.1
  Top Layer w6: v1(2597.09,2762.91) 2624.09,2762.91 2634.27,2773.1 2650.06,2773.1 ; 3779.95,2739.71 3798.04,2739.71 3798.39,2739.37 U101.7
  Top Layer w9: 2650.06,2773.1 2696.97,2773.1 2739.87,2816 3587.13,2816 3663.42,2739.71 3779.95,2739.71
  Bottom Layer w6: J101.6@2490,2760 2594.17,2760 v1(2597.09,2762.91)
D1-_A: L102.3 U101.39 U104.5 U104.6 | length 1191.5
  Top Layer w5: 4009.03,3437 4009.03,3700.36 4009.37,3700.7 4009.37,3757 4009.03,3757.34 4009.03,3840.09 4009.03,3881.46 4009.37,3881.8 4009.37,3937 4009.03,3937.34 4009.03,3979.41 4008.5,3979.94 4008.5,4010.5 4015.73,4017.73 L102.3
  Top Layer w6: 3929.18,2928.32 3929.18,2910.22 3929.53,2909.88 U101.39
  Top Layer w9: 3929.18,2928.32 3929.19,2983.19 4009.03,3063.03 4009.03,3437
D1-_B: L106.3 R114.2 U101.30 U106.5 U106.6 | length 1492.6
  Top Layer w5: 4816,2710.97 5079.36,2710.97 5079.7,2710.63 5136,2710.63 5136.34,2710.97 5219.09,2710.97 5260.46,2710.97 5260.8,2710.63 5316,2710.63 5316.34,2710.97 5358.41,2710.97 5358.94,2711.5 5389.5,2711.5 5396.73,2704.27 L106.3
  Top Layer w6: U101.30 4001.61,2700 4001.96,2700.34 4020.05,2700.34
  Top Layer w9: 4020.05,2700.34 4214.21,2700.34 4251.87,2738 4420.03,2738 4431.76,2738 R114.2 4481.7,2738 4503.48,2738 4694,2738 4720,2712 ; 4720.16,2710.97 4816,2710.97
D1-_DP: J102.6 L102.4 | length 228
  Top Layer w9: L102.4 4015.73,4128.77 4008.5,4136 4008.5,4191.63 4011.33,4194.46 4011.33,4266.67 4021.52,4276.85 J102.6
D1-_HDMI: J103.6 L106.4 | length 226.4
  Top Layer w9: L106.4 5507.77,2704.27 5515,2711.5 5579.5,2711.5 5588.24,2702.76 5649.82,2702.76 5660,2692.57 J103.6
D2+: J101.7 U101.8 | length 1324.8
  Top Layer w6: J101.7@2515,2745 2580,2745 2591.96,2733.04 2619.37,2733.04 ; 3779.95,2719.34 3798.04,2719.34 3798.39,2719.68 U101.8
  Top Layer w9: 2619.37,2733.04 2671.96,2733.04 2685.5,2719.5 ; 2685.5,2719.34 3779.95,2719.34
D2+_A: L103.1 U101.38 U105.1 U105.10 | length 1257.7
  Top Layer w5: L103.1 4052.27,4017.73 4059.5,4010.5 4059.5,3964 4059.5,3960.06 4063.97,3955.59 4063.97,3937.34 4063.63,3937 4063.63,3881.8 4063.97,3881.46 4063.97,3814.53 4063.97,3757.34 4063.63,3757 4063.63,3700.7 4063.97,3700.36 4063.97,3437
  Top Layer w6: U101.38 4001.61,2857.48 4001.96,2857.14 4020.05,2857.14
  Top Layer w9: 4020.05,2857.14 4034.14,2857.14 4063.97,2886.97 4063.97,3437
D2+_B: L107.1 R113.2 U101.29 U107.1 U107.10 | length 1492.5
  Top Layer w5: 4816,2651.03 5079.36,2651.03 5079.7,2651.37 5136,2651.37 5136.34,2651.03 5193.53,2651.03 5260.46,2651.03 5260.8,2651.37 5316,2651.37 5316.34,2651.03 5334.59,2651.03 5339.06,2655.5 5343,2655.5 5389.5,2655.5 5396.73,2662.73 L107.1
  Top Layer w6: U101.29 4001.61,2680.32 4001.96,2679.97 4020.05,2679.97
  Top Layer w9: 4020.05,2679.97 4220.03,2679.97 4268,2632 4435.7,2632 R113.2 4477.76,2632 4698.13,2632 4717.16,2651.03 4816,2651.03
D2+_DP: J102.7 L103.2 | length 230.2
  Top Layer w9: J102.7 4041.2,4276.85 4051.39,4266.67 4051.39,4205.74 4059.5,4197.63 4059.5,4136 4052.27,4128.77 L103.2
D2+_HDMI: J103.1 L105.2 | length 228.8
  Top Layer w9: L105.2 5507.77,2802.73 5515,2795.5 5551.87,2795.5 5566.56,2780.82 5649.82,2780.82 5660,2791 J103.1
D2-: J101.9 U101.9 | length 1310.7
  Top Layer w6: J101.9@2530,2700 2575,2700 2589.04,2714.04 2619.95,2714.04 ; 3779.95,2700.34 3798.04,2700.34 3798.39,2700 U101.9
  Top Layer w9: 2619.95,2714.04 2664.09,2714.04 2677.63,2700.5 ; 2677.63,2700.34 3779.95,2700.34
D2-_A: L103.3 U101.37 U105.2 U105.9 | length 1289.1
  Top Layer w5: 4082.97,3437 4082.97,3700.36 4083.32,3700.7 4083.32,3757 4082.97,3757.34 4082.97,3881.46 4083.32,3881.8 4083.32,3937 4082.97,3937.34 4082.97,3963.46 4078.5,3967.94 4078.5,4010.5 4085.73,4017.73 L103.3
  Top Layer w6: U101.37 4001.61,2837.8 4001.96,2838.14 4020.05,2838.14
  Top Layer w9: 4020.05,2838.14 4042.01,2838.14 4082.97,2879.1 4082.97,3437
D2-_B: L107.3 R112.2 U101.28 U107.2 U107.9 | length 1495.7
  Top Layer w5: 4816,2632.03 5079.36,2632.03 5079.7,2631.68 5136,2631.68 5136.34,2632.03 5260.46,2632.03 5260.8,2631.68 5316,2631.68 5316.34,2632.03 5342.46,2632.03 5346.94,2636.5 5389.5,2636.5 5396.73,2629.27 L107.3
  Top Layer w6: U101.28 4001.61,2660.63 4001.96,2660.97 4020.05,2660.97
  Top Layer w9: 4020.05,2660.97 4212.16,2660.97 4260.13,2613 4431.76,2613 R112.2 4481.7,2613 4706,2613 4725.03,2632.03 4816,2632.03
D2-_DP: J102.9 L103.4 | length 230.2
  Top Layer w9: J102.9 4080.57,4276.85 4070.39,4266.67 4070.39,4213.61 4078.5,4205.5 4078.5,4136 4085.73,4128.77 L103.4
D2-_HDMI: J103.3 L105.4 | length 228.8
  Top Layer w9: L105.4 5507.77,2769.27 5515,2776.5 5544,2776.5 5558.69,2761.81 5649.81,2761.81 5660,2751.63 J103.3
D3+: J101.10 U101.10 | length 1374.6
  Top Layer w6: v1(2599.17,2684.17) 2626.17,2684.17 2636.36,2673.99 2645.14,2673.99 ; 3779.95,2679.97 3798.04,2679.97 3798.39,2680.31 U101.10
  Top Layer w9: 2645.14,2673.99 2686.01,2673.99 2735,2625 3663.13,2625 3718.1,2679.97 3779.95,2679.97
  Bottom Layer w6: J101.10@2495,2690 J101.10@2500.83,2684.17 ; J101.10@2511,2686 2597.35,2686 v1(2599.17,2684.17)
D3+_A: L104.1 U101.36 U105.4 U105.7 | length 1344.5
  Top Layer w5: L104.1 4117.27,4017.73 4124.5,4010.5 4124.5,3976 4124.5,3972.06 4125.03,3971.54 4125.03,3937.34 4124.69,3937 4124.69,3881.8 4125.03,3881.46 4125.03,3840.09 4125.03,3757.34 4124.69,3757 4124.69,3700.7 4125.03,3700.36 4125.03,3437
  Top Layer w6: U101.36 4001.61,2818.11 4001.96,2817.77 4020.05,2817.77
  Top Layer w9: 4020.05,2817.77 4074.77,2817.77 4125.03,2868.03 4125.03,3437
D3+_B: L108.1 R111.2 U101.27 U107.4 U107.7 | length 1542.9
  Top Layer w5: 4816,2589.97 5079.36,2589.97 5079.7,2590.32 5136,2590.32 5136.34,2589.97 5219.09,2589.97 5260.46,2589.97 5260.8,2590.32 5316,2590.32 5316.34,2589.97 5350.54,2589.97 5351.06,2590.5 5355,2590.5 5389.5,2590.5 5396.73,2597.73 L108.1
  Top Layer w6: U101.27 4001.61,2640.94 4001.96,2640.6 4020.05,2640.6
  Top Layer w9: 4020.05,2640.6 4161.4,2640.6 4284,2518 4426.45,2518 4436.7,2518 R111.2 4476.76,2518 4493.01,2518 4683.13,2518 4755.1,2589.97 4816,2589.97
D3+_DP: J102.10 L104.2 | length 232.7
  Top Layer w9: J102.10 4100.26,4276.85 4110.44,4266.67 4110.44,4218.68 4124.5,4204.63 4124.5,4136 4117.27,4128.77 L104.2
D3-: J101.12 U101.11 | length 1402.9
  Top Layer w6: v1(2599.8,2644.8) 2626.8,2644.8 2636.99,2654.99 2645.14,2654.99 ; 3779.95,2660.97 3798.04,2660.97 3798.39,2660.63 U101.11
  Top Layer w9: 2645.14,2654.99 2678.14,2654.99 2727.13,2606 3671,2606 3725.97,2660.97 3779.95,2660.97
  Bottom Layer w6: J101.12@2473.62,2644 v1@2599.8,2644
D3-_A: L104.3 U101.35 U105.5 U105.6 | length 1376
  Top Layer w5: 4144.03,3437 4144.03,3700.36 4144.37,3700.7 4144.37,3757 4144.03,3757.34 4144.03,3840.09 4144.03,3881.46 4144.37,3881.8 4144.37,3937 4144.03,3937.34 4144.03,3979.41 4143.5,3979.94 4143.5,4010.5 4150.73,4017.73 L104.3
  Top Layer w6: U101.35 4001.61,2798.43 4001.96,2798.77 4020.05,2798.77
  Top Layer w9: 4020.05,2798.77 4082.64,2798.77 4144.03,2860.16 4144.03,3437
D3-_B: L108.3 R110.2 U101.26 U107.5 U107.6 | length 1547.8
  Top Layer w5: 4816,2570.97 5079.36,2570.97 5079.7,2570.63 5136,2570.63 5136.34,2570.97 5219.09,2570.97 5260.46,2570.97 5260.8,2570.63 5316,2570.63 5316.34,2570.97 5358.41,2570.97 5358.94,2571.5 5389.5,2571.5 5396.73,2564.27 L108.3
  Top Layer w6: U101.26@3970.87,2621.26 4001.61,2621.26 4001.96,2621.6 4020.05,2621.6
  Top Layer w9: 4020.05,2621.6 4153.53,2621.6 4276.13,2499 4425.1,2499 4430.76,2499 R110.2 4482.7,2499 4500.44,2499 4691,2499 4762.97,2570.97 4816,2570.97
D3-_DP: J102.12 L104.4 | length 232.7
  Top Layer w9: J102.12 4139.63,4276.85 4129.44,4266.67 4129.44,4226.56 4143.5,4212.5 4143.5,4136 4150.73,4128.77 L104.4
GND: C101.2 C102.2 C103.2 C104.2 C105.2 C106.1 C107.1 C108.1 C109.1 C110.2 C111.1 C112.1 C113.1 J101.2 J101.5 J101.8 J101.11 J101.16 J101.19 J101.21 J102.2 J102.5 J102.8 J102.11 J102.16 J102.19 J102.21 J102.22 J103.2 J103.5 J103.8 J103.11 J103.17 J103.20 J103.21 J103.22 J103.23 J104.5 Q101.2 R101.1 R103.1 R104.1 R105.1 R119.1 R121.2 R124.2 R127.1 R129.1 U101.1 U101.17 U101.22 U101.43 U102.8 U103.2 U104.3 U105.3 U106.3 U107.3 | length 2481
  Top Layer w9: v1(3969,3661) U104.3 ; v1(4104,3661) U105.3 ; v1(5050,2611) U107.3 ; v1(5050,2751) U106.3
  Top Layer w11: U101.17 3847.52,2542.52 3870,2565 ; U101.1 3852.52,2857.48 3880,2830 ; v1(3920,2570) 3947.48,2542.52 U101.22 ; U102.8 v1(3989.57,2064.57) ; J102.2 v1(3942.83,4394.21) ; J102.5@4001.89,4330 v1(4001.89,4394.21) ; J102.8 v1(4060.94,4394.21) ; J102.11@4120,4330 v1(4120,4394.21) ; J102.16 v1(4218.43,4394.21) ; J102.19@4277.48,4330 v1(4277.48,4394.21) ; J103.17 v1(5765,2476.04) ; J103.11 v1(5759.15,2594.15) ; J103.8 v1(5759.15,2653.2) ; J103.5 v1(5759.15,2712.26) ; J103.2 v1(5759.15,2771.32)
  Top Layer w20: J101.19 v2(2582.99,2507.01) ; J101.11 v1(2569.49,2664.49) ; J101.5 v1(2567.6,2782.6) ; v1(3535.03,1910.03) R124.2 ; v1(3625,1766.3) C113.1 ; v1(4185.03,4020.35) R101.1 ; R121.2 v1(4545.03,2079.97) ; v1(5015.35,4384.97) R127.1 ; v1(5045,3376.3) C105.2@5045,3400 ; v1(5080,3376.3) C105.2@5080,3400 ; v1(5110,3376.3) C105.2@5110,3400 ; Q101.2@5150,4185 v1(5150,4208.7) ; v1(5160.35,4284.97) R129.1 ; v1(5190,3421.3) C104.2@5190,3445 ; v1(5220,3421.3) C104.2@5220,3445 ; C102.2@5315,3325 v1(5315,3348.7) ; C102.2@5355,3325 v1(5355,3348.7) ; U103.2@5390,3705 v1(5390,3728.7) ; C102.2@5395,3325 v1(5395,3348.7) ; C102.2@5430,3325 v1(5430,3348.7) ; C103.2@5525,3685 v1(5525,3708.7) ; C103.2@5555,3685 v1(5555,3708.7) ; C101.2@5620,3685 v1(5620,3708.7) ; C101.2@5650,3690 v1(5650,3713.7) ; J104.5@5725,3695 J104.5@5725,3780 ; J104.5@5751.1,3691.99 J104.5@5751.1,3778.9 ; J104.5@5780,3695 J104.5@5780,3775
  Bottom Layer w20: J101.16 v1(2568.54,2566.06) ; J101.8 v1(2568.54,2723.54) ; J101.2 v1(2568.35,2841.65) ; C110.2 2655,2475 v1(2665,2485) ; C109.1@3870,2625 3885,2625 v1(3900,2610) ; v1(3895,2825) C106.1 ; v1(3900,2795) C108.1 ; R103.1 v1(4150.03,4525.95) ; R104.1 v1(4200.03,4525.95) ; R105.1 v1(4255.03,4525.95) ; C111.1 v1(4385,4235) ; v1(5599.97,2340.03) R119.1 ; C112.1 v1(5605,2535)
  other v1: 5725,3715 5751.1,3735 5780,3750
HPD: J101.18 U101.18 | length 1459.6
  Top Layer w8: v1(2825,2450) 3155,2450 3175,2430 3805,2430 3870.47,2495.47 U101.18
  Bottom Layer w8: J101.18 2688.31,2526.69 2765,2450 v1(2825,2450)
HPD_A: J102.18 R105.2 U101.16 | length 2389
  Top Layer w8: v1(3785,2500) 3785,2540 3807.2,2562.2 U101.16 ; v1(4257.74,4252.74) J102.18
  Bottom Layer w8: v1(3785,2500) 3765,2500 3735,2530 3735,3755 4232.74,4252.74 v1(4257.74,4252.74) 4255.03,4255.45 R105.2
HPD_B: J103.19 R119.2 U101.15 | length 2143.2
  Top Layer w8: v1(3755,2465) 3755,2535 3801.89,2581.89 U101.15 ; v1(5635,2415) 5656.67,2436.67 J103.19
  Bottom Layer w8: v1(3755,2465) 3795,2425 5485,2425 5495,2415 v1(5635,2415)
HS_SEL: R122.2 U101.2 U101.5 | length 2020.8
  Top Layer w8: v1(3795,2845) 3802.2,2837.8 U101.2 ; v2@3795.26,2778.74 U101.5 ; v1(5035,4135) R122.2
  Bottom Layer w8: v2(3795,2778.48) 3795,2965 4965,4135 v1(5035,4135)
NetD101_2: D101.2 JP101.2 | length 128.6
  Bottom Layer w40: D101.2 2845,2400 JP101.2
NetJP102_1: JP102.1 R120.1 | length 89
  Top Layer w8: JP102.1 R120.1
NetJP102_3: JP102.3 R121.1 | length 89
  Top Layer w8: JP102.3 R121.1
NetQ101_3: Q101.3 R110.1 R111.1 R112.1 R113.1 R114.1 R115.1 R116.1 R117.1 | length 2192
  Top Layer w8: R110.1 4518.03,2473.03 v1(4530,2461.06) ; R111.1 4518.03,2538.03 v1(4530,2550) ; R112.1 4518.03,2588.03 v1(4530,2576.06) ; R113.1 4518.03,2653.03 v1(4530,2665) ; R114.1 4518.03,2713.03 v1(4530,2701.06) ; R115.1 4518.03,2778.03 v1(4530,2790) ; R116.1 4518.03,2828.03 v1(4530,2816.06) ; R117.1 4518.03,2893.03 v1(4530,2905) ; v1(5185,4055) Q101.3@5185,4093.74
  Bottom Layer w8: v1(4530,2461.06) 4530,3040 4975,3485 4975,3845 v1(5185,4055)
NetR124_1: R124.1 U102.15 | length 86.9
  Top Layer w9: R124.1@3601.94,1911.02 U102.15
NetR126_1: R126.1 SW101.3 | length 149.1
  Top Layer w8: R126.1 SW101.3@5284.05,4534.05
NetR127_2: R127.2 SW101.1 | length 153.8
  Top Layer w8: R127.2 SW101.1@5081.27,4538.73
OE: JP102.2 U101.25 | length 960.3
  Top Layer w8: U101.25 v2@4004.74,2601.57 ; v1(4070,2390) v1(4070,2460)
  Bottom Layer w8: v2(4005,2601.83) 4005,2525 v1(4070,2460) ; v1(4070,2390) 4185,2390 4445,2130 JP102.2
PORT_SEL: R122.1 R123.1 R128.2 SW101.2 | length 428.4
  Top Layer w8: R122.1 R123.1 5130,4260.98 5130,4365 5150.03,4385.03 R128.2 SW101.2@5183.73,4533.73
SB_SEL: R123.2 U102.1 | length 4662.1
  Top Layer w8: U102.1 v1(3994.57,1885.43) ; v1(5085,4140) R123.2
  Bottom Layer w8: v1(3994.57,1885.43) 4164.57,1885.43 4225,1825 5385,1825 5915,2355 5915,3790 5565,4140 v1(5085,4140)
SCL_B: J103.15 Q102.3 R109.1 | length 601.6
  Top Layer w9: Q102.3 5446.26,2336.26 5625.41,2515.41 J103.15
SDA_B: J103.16 Q103.3 R108.1 | length 659.7
  Top Layer w9: Q103.3 5329.54,2176.26 5649,2495.72 J103.16
TMDS_OFFSET: Q101.1 R128.1 R129.2 | length 205.1
  Top Layer w8: Q101.1@5225.03,4178.97 R128.1@5225.03,4384.11
pads on no net: J102.23 J102.24 J102.25 J103.14 J104.2 J104.3 J104.4 J104.10 J104.11 SW101.4 SW101.5 U102.2 U102.3 U102.4 U102.12 U102.13 U102.14 U103.4

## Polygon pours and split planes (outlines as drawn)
+3V3 on Top Layer "Bottom Layer-No Net" (solid, remove dead copper, pour order 1002): 5015,3510 5265,3510 5265,3705 4995,3705 4995,3510 5015,3510
+3V3_USB on Top Layer "Bottom Layer-No Net" (solid, remove dead copper, pour order 1001): 5370,3750 5160,3750 5160,3855 5370,3855 5370,3750
+5V on Top Layer "Bottom Layer-No Net" (solid, remove dead copper, pour order 1000): 5795,3580 5700,3580 5665,3615 5660,3620 5490,3620 5490,3715 5480,3725 5415,3725 5410,3720 5410,3655 5375,3655 5370,3660 5370,3725 5290,3725 5290,3500 5685,3500 5695,3510 5795,3510 5795,3580
+3V3 on Bottom Layer "Bottom Layer-No Net" (solid, remove dead copper, pour order 1003): 2950,2425 3145,2425 3145,2255 2950,2255 2950,2425
GND on InternalPlane1 (split plane): 5923.48,4878.35 5946.56,4873.76 5968.84,4866.19 5989.94,4855.79 6009.51,4842.71 6027.2,4827.2 6042.71,4809.51 6055.78,4789.94 6066.19,4768.84 6073.76,4746.56 6078.35,4723.48 6079.82,4701.05 6079.61,4700 6079.61,1700 6079.82,1698.95 6078.35,1676.52 6073.76,1653.44 6066.19,1631.16 6055.79,1610.06 6042.71,1590.49 6027.2,1572.8 6009.51,1557.29 5989.94,1544.21 5968.84,1533.81 5946.56,1526.24 5923.48,1521.65 5901.05,1520.18 5900,1520.39 3300,1520.39 3299.74,1520.34 3299.07,1520.21 3297.5,1520.1 3274.35,1521.62 3251.59,1526.15 3229.61,1533.61 3208.8,1543.87 3189.51,1556.76 3172.06,1572.06 3156.76,1589.51 3143.87,1608.8 3133.61,1629.61 3126.15,1651.59 3121.62,1674.35 3120.3,1694.53 3120.39,1695 3120.39,1998 3118.84,2005.8 3117.07,2008.45 3114.42,2012.42 2904.42,2222.42 2897.8,2226.84 2890,2228.39 2397.28,2228.39 2317.39,2254.75 2317.39,2310.61 2394,2310.61 2401.8,2312.16 2408.42,2316.58 2411.78,2321.61 2528,2321.61 2535.8,2323.16 2542.42,2327.58 2546.84,2334.2 2548.39,2342 2548.39,2381 2546.84,2388.8 2542.42,2395.42 2535.8,2399.84 2528,2401.39 2414.39,2401.39 2414.39,2960 2412.84,2967.8 2408.42,2974.42 2401.8,2978.84 2394,2980.39 2317.39,2980.39 2317.39,3035.08 2404.16,3062.61 2890,3062.61 2897.8,3064.16 2904.42,3068.58 3114.42,3278.58 3117.07,3282.55 3118.84,3285.2 3120.39,3293 3120.39,4700 3120.18,4701.05 3121.65,4723.48 3126.24,4746.56 3133.81,4768.84 3144.22,4789.94 3157.29,4809.51 3172.8,4827.2 3190.49,4842.71 3210.06,4855.79 3231.16,4866.19 3253.44,4873.76 3276.52,4878.35 3298.95,4879.82 3300,4879.61 5900,4879.61 5901.05,4879.82
+5V on InternalPlane2 (split plane): 6079.61,1700 6079.82,1698.95 6078.35,1676.52 6073.76,1653.44 6066.19,1631.16 6055.79,1610.06 6042.71,1590.49 6027.2,1572.8 6009.51,1557.29 5989.94,1544.21 5968.84,1533.81 5946.56,1526.24 5923.48,1521.65 5901.05,1520.18 5900,1520.39 3300,1520.39 3299.74,1520.34 3299.07,1520.21 3297.5,1520.1 3274.35,1521.62 3251.59,1526.15 3229.61,1533.61 3208.8,1543.87 3189.51,1556.76 3172.06,1572.06 3156.76,1589.51 3143.87,1608.8 3133.61,1629.61 3126.15,1651.59 3121.62,1674.35 3120.3,1694.53 3120.39,1695 3120.39,1964.8 3710.78,1964.8 3892.79,1782.79 3896.1,1780.58 3900,1779.8 4880,1779.8 4883.9,1780.58 4887.21,1782.79 5272.21,2167.79 5274.42,2171.1 5275.2,2175 5275.2,2430.78 5309.22,2464.8 5600,2464.8 5603.9,2465.58 5607.21,2467.79 5654.22,2514.8 5840,2514.8 5843.9,2515.58 5847.21,2517.79 5849.42,2521.1 5850.2,2525 5850.2,3050 5849.42,3053.9 5847.21,3057.21 5460.2,3444.22 5460.2,4079.8 6079.61,4079.8
+3V3 on InternalPlane2 (split plane): 5923.48,4878.35 5946.56,4873.76 5968.84,4866.19 5989.94,4855.79 6009.51,4842.71 6027.2,4827.2 6042.71,4809.51 6055.78,4789.94 6066.19,4768.84 6073.76,4746.56 6078.35,4723.48 6079.82,4701.05 6079.61,4700 6079.61,4100.2 5450,4100.2 5446.1,4099.42 5442.79,4097.21 5440.58,4093.9 5439.8,4090 5439.8,3440 5440.58,3436.1 5442.79,3432.79 5829.8,3045.78 5829.8,2535.2 5650,2535.2 5646.1,2534.42 5642.79,2532.21 5595.78,2485.2 5305,2485.2 5301.1,2484.42 5297.79,2482.21 5257.79,2442.21 5255.58,2438.9 5254.8,2435 5254.8,2179.22 4875.78,1800.2 3904.22,1800.2 3722.21,1982.21 3718.9,1984.42 3715,1985.2 3120.39,1985.2 3120.39,1998 3118.84,2005.8 3117.07,2008.45 3114.42,2012.42 2904.42,2222.42 2897.8,2226.84 2890,2228.39 2397.28,2228.39 2317.39,2254.75 2317.39,2310.61 2394,2310.61 2401.8,2312.16 2408.42,2316.58 2411.78,2321.61 2528,2321.61 2535.8,2323.16 2542.42,2327.58 2546.84,2334.2 2548.39,2342 2548.39,2381 2546.84,2388.8 2542.42,2395.42 2535.8,2399.84 2528,2401.39 2414.39,2401.39 2414.39,2960 2412.84,2967.8 2408.42,2974.42 2401.8,2978.84 2394,2980.39 2317.39,2980.39 2317.39,3035.08 2404.16,3062.61 2890,3062.61 2897.8,3064.16 2904.42,3068.58 3114.42,3278.58 3117.07,3282.55 3118.84,3285.2 3120.39,3293 3120.39,4700 3120.18,4701.05 3121.65,4723.48 3126.24,4746.56 3133.81,4768.84 3144.22,4789.94 3157.29,4809.51 3172.8,4827.2 3190.49,4842.71 3210.06,4855.79 3231.16,4866.19 3253.44,4873.76 3276.52,4878.35 3298.95,4879.82 3300,4879.61 5900,4879.61 5901.05,4879.82

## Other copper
InternalPlane2 (plane layer: these items are gaps in the copper):
  lines w20: 3100,1975 3715,1975 3900,1790 4880,1790 5265,2175 5265,2435 5305,2475 5600,2475 5650,2525 5840,2525 5840,3050 5450,3440 5450,4090 6100,4090

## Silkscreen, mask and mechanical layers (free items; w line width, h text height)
Top Overlay:
  rectangle: 5005,1545 5905,1750
  text "DP_OUTPUT" at 3555,4230 h60
  text "HDMI_OUTPUT" at 5595,2480 h60 r270
  text "+3V3" at 2925,2250 h60
  text "OE" at 4425,2069.19 h60 r270
  text "PI3WVR12412ZHE_DP HDMI SW_EVB" at 4900,1850 h60
  text "REV.A" at 4900,1780 h60
  text "Date:2013.12.9" at 5155,1780 h60
  text "S/N:" at 4900,1645 h60
Bottom Overlay:
  text "1351DB255" at 5685,1545 h60
Mechanical 1:
  the board outline again, w8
